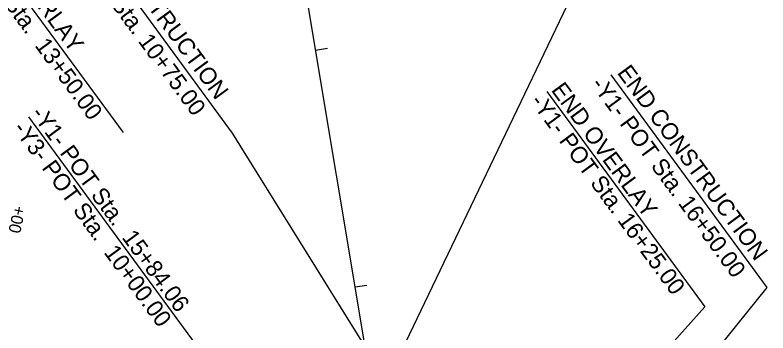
# Model space of a CAD drawing. Extents: x 1762196 to 1766326, y 709922 to 713142.
# Drawn here: x 1763712.3 to 1764026, y 712488 to 712620.3 of the extents above; entities that cross this region are included whole.
import ezdxf

# ---------------------------------------------------------------- set-up
doc = ezdxf.new("R2010")
doc.units = 0
for name, color, linetype in [('Prop Dimension', 7, 'Continuous'), ('Prop Horizontal Alignment', 7, 'Continuous'), ('Prop Horizontal Alignment Station Label', 7, 'Continuous'), ('Prop Horizontal Alignment Tick Small', 7, 'Continuous')]:
    doc.layers.add(name, color=color, linetype=linetype)

msp = doc.modelspace()

# ---------------------------------------------------------------- linework, layer by layer
at = {"layer": 'Prop Horizontal Alignment'}
msp.add_line((1763870.46, 712408.3), (1763783.92, 712926.06), dxfattribs=at)
at = {"layer": 'Prop Horizontal Alignment Station Label'}
for p, q in [((1763984.12, 712711.37), (1763862.22, 712457.62)), ((1763686.48, 712667.75), (1763757.27, 712571.42)), ((1763735.91, 712662.18), (1763802.81, 712571.14)), ((1763960.53, 712595.41), (1764025.58, 712506.91)), ((1763933.81, 712588.47), (1763999.72, 712498.79)), ((1763717.89, 712577.9), (1763787.34, 712483.39)), ((1763802.81, 712571.14), (1763858.1, 712482.28)), ((1764025.58, 712506.91), (1763934.95, 712394.55)), ((1763999.72, 712498.79), (1763910.5, 712399.76))]:
    msp.add_line(p, q, dxfattribs=at)
at = {"layer": 'Prop Horizontal Alignment Tick Small'}
for p, q in [((1763842.42, 712606.39), (1763837.49, 712605.57)), ((1763858.91, 712507.76), (1763853.98, 712506.94))]:
    msp.add_line(p, q, dxfattribs=at)

# ---------------------------------------------------------------- texts
at = {"layer": 'Prop Dimension'}
msp.add_text('+00', height=5, rotation=257.9589, dxfattribs=at).set_placement((1763711.84, 712541.22))
at = {"layer": 'Prop Horizontal Alignment Station Label'}
for s, p in [('BEGIN OVERLAY', (1763690.83, 712665.33)), ('END CONSTRUCTION', (1763738.17, 712663.28)), ('-Y1- POT Sta.  13+50.00', (1763682.36, 712659.11)), ('-Y3- POT Sta. 10+75.00', (1763726.95, 712658.82)), ('END CONSTRUCTION', (1763962.93, 712596.23)), ('END OVERLAY', (1763935.42, 712589)), ('-Y1- POT Sta. 16+50.00', (1763951.97, 712591.39)), ('-Y1- POT Sta. 16+25.00', (1763926.71, 712584.28)), ('-Y1- POT Sta.  15+84.06', (1763718.64, 712579.21)), ('-Y3- POT Sta.  10+00.00', (1763711.14, 712572.97))]:
    msp.add_text(s, height=7, rotation=306.3131, dxfattribs=at).set_placement(p)

doc.saveas('drawing.dxf')
